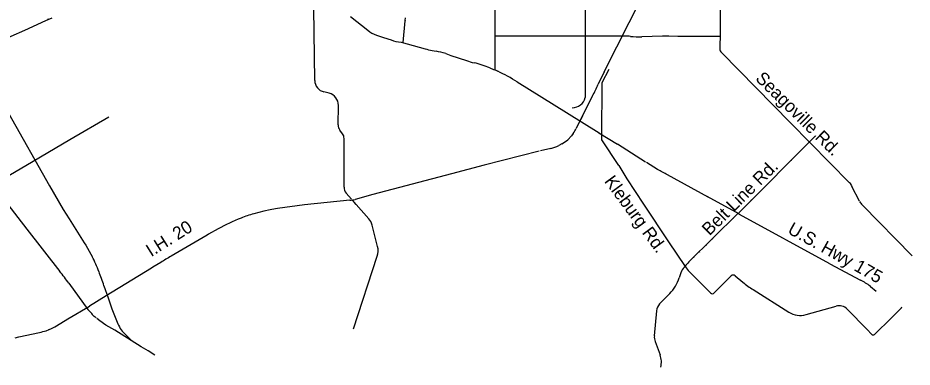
# Model space of a CAD drawing. Extents: x 105094 to 105814, y -291615 to -291123.
# Drawn here: x 105478.5 to 105563.1, y -291541 to -291508 of the extents above; entities that cross this region are included whole.
import ezdxf

# ---------------------------------------------------------------- set-up
doc = ezdxf.new("R2010")
doc.units = 0
doc.layers.add('G_MAP', color=7, linetype='Continuous')

msp = doc.modelspace()

# ---------------------------------------------------------------- linework, layer by layer
at = {"layer": 'G_MAP'}
for p, q in [((105532.097, -291466.509), (105532.215, -291515.51)), ((105534.008, -291513.065), (105538.513, -291504.143)), ((105506.612, -291513.872), (105506.522, -291507.026)), ((105479.182, -291509.112), (105481.174, -291508.211)), ((105481.174, -291508.211), (105481.762, -291507.946)), ((105481.432, -291508.143), (105481.387, -291508.059)), ((105509.99, -291507.821), (105511.634, -291509.112)), ((105514.97, -291510.304), (105515.161, -291508.247)), ((105515.165, -291508.209), (105515.214, -291507.962)), ((105476.385, -291510.349), (105479.178, -291509.112)), ((105512.464, -291509.593), (105513.113, -291509.832)), ((105513.113, -291509.832), (105513.837, -291510.042)), ((105523.79, -291509.69), (105523.674, -291509.69)), ((105535.712, -291509.689), (105523.79, -291509.69)), ((105539.514, -291509.687), (105537.56, -291509.74)), ((105514.789, -291510.259), (105517.053, -291510.888)), ((105517.725, -291511.047), (105518.093, -291511.113)), ((105506.532, -291511.428), (105506.625, -291511.428)), ((105519.007, -291511.343), (105519.508, -291511.508)), ((105519.508, -291511.508), (105520.983, -291511.999)), ((105545.101, -291511.247), (105551.638, -291517.886)), ((105523.191, -291512.703), (105523.528, -291512.839)), ((105523.528, -291512.839), (105523.761, -291512.916)), ((105523.761, -291512.916), (105523.942, -291513.007)), ((105534.008, -291513.065), (105533.443, -291514.247)), ((105525.77, -291514.016), (105529.27, -291516.191)), ((105507.979, -291515.098), (105507.484, -291514.973)), ((105532.91, -291515.352), (105531.996, -291517.131)), ((105508.83, -291518.096), (105508.847, -291516.238)), ((105529.27, -291516.191), (105531.86, -291517.796)), ((105477.644, -291516.979), (105481.513, -291523.864)), ((105531.996, -291517.131), (105531.368, -291518.414)), ((105531.96, -291517.215), (105531.783, -291517.564)), ((105531.86, -291517.796), (105533.539, -291518.849)), ((105509.243, -291518.925), (105508.993, -291518.584)), ((105557.231, -291523.567), (105551.638, -291517.886)), ((105509.383, -291523.974), (105509.39, -291519.371)), ((105530.911, -291519.111), (105530.555, -291519.489)), ((105531.068, -291518.901), (105530.911, -291519.111)), ((105533.508, -291518.833), (105535.264, -291519.896)), ((105533.787, -291519.489), (105533.787, -291519.256)), ((105535.388, -291521.94), (105533.787, -291519.489)), ((105553.994, -291519.129), (105546.735, -291526.416)), ((105554.012, -291519.13), (105553.969, -291519.171)), ((105528.943, -291520.315), (105527.972, -291520.541)), ((105530.006, -291519.877), (105529.721, -291520.027)), ((105537.925, -291521.601), (105535.264, -291519.896)), ((105479.979, -291521.549), (105476.14, -291523.793)), ((105539.062, -291522.292), (105538.015, -291521.652)), ((105551.663, -291521.426), (105551.715, -291521.5)), ((105509.348, -291522.702), (105509.409, -291522.702)), ((105519.546, -291522.705), (105512.109, -291524.688)), ((105543.858, -291524.92), (105539.998, -291522.812)), ((105509.425, -291523.629), (105509.341, -291523.632)), ((105510.077, -291525.114), (105509.59, -291524.54)), ((105558.183, -291525.319), (105557.46, -291523.922)), ((105477.347, -291525.34), (105479.363, -291527.943)), ((105509.935, -291525.224), (105505.653, -291525.66)), ((105510.342, -291525.395), (105510.2, -291525.234)), ((105510.523, -291525.608), (105510.342, -291525.395)), ((105512.109, -291524.688), (105510.439, -291525.134)), ((105546.522, -291526.374), (105543.702, -291524.827)), ((105547.881, -291525.182), (105547.936, -291525.24)), ((105482.443, -291525.563), (105482.518, -291525.505)), ((105501.801, -291526.251), (105500.84, -291526.507)), ((105502.383, -291526.128), (105501.801, -291526.251)), ((105505.653, -291525.66), (105503.078, -291526.008)), ((105511.732, -291526.962), (105510.523, -291525.608)), ((105547.407, -291525.676), (105547.445, -291525.724)), ((105563.15, -291530.472), (105558.44, -291525.674)), ((105483.37, -291526.987), (105484.785, -291529.257)), ((105546.615, -291526.516), (105542.019, -291531.059)), ((105546.147, -291526.919), (105546.192, -291526.968)), ((105546.825, -291526.551), (105546.522, -291526.374)), ((105555.361, -291531.218), (105546.829, -291526.551)), ((105479.363, -291527.943), (105482.489, -291531.947)), ((105497.464, -291527.927), (105496.556, -291528.427)), ((105512.563, -291529.597), (105512.05, -291527.561)), ((105545.672, -291527.375), (105545.727, -291527.443)), ((105496.427, -291528.515), (105493.026, -291530.51)), ((105496.556, -291528.427), (105496.43, -291528.515)), ((105544.991, -291528.037), (105545.049, -291528.101)), ((105484.785, -291529.257), (105484.937, -291529.474)), ((105484.937, -291529.474), (105485.431, -291530.32)), ((105543.628, -291529.429), (105543.677, -291529.471)), ((105544.232, -291528.835), (105544.274, -291528.88)), ((105485.431, -291530.32), (105485.557, -291530.539)), ((105510.267, -291537.384), (105512.531, -291530.503)), ((105542.989, -291530.065), (105543.034, -291530.12)), ((105492.041, -291531.101), (105491.279, -291531.557)), ((105542.459, -291530.578), (105542.52, -291530.63)), ((105555.361, -291531.218), (105558.274, -291532.784)), ((105491.153, -291531.631), (105486.868, -291534.26)), ((105491.279, -291531.557), (105491.153, -291531.631)), ((105541.256, -291532.09), (105541.109, -291532.548)), ((105541.666, -291531.46), (105541.59, -291531.56)), ((105542.063, -291531.964), (105544.083, -291533.989)), ((105544.424, -291533.989), (105546.036, -291532.374)), ((105546.393, -291532.357), (105547.124, -291532.966)), ((105483.338, -291533.068), (105485.127, -291535.542)), ((105486.668, -291533.301), (105487.055, -291534.46)), ((105548.103, -291533.677), (105551.49, -291535.806)), ((105559.198, -291533.368), (105559.754, -291533.813)), ((105486.868, -291534.26), (105485.282, -291535.228)), ((105487.055, -291534.46), (105487.407, -291535.49)), ((105540.209, -291534.049), (105539.255, -291535.032)), ((105483.244, -291536.452), (105485.282, -291535.228)), ((105485.502, -291535.945), (105485.127, -291535.542)), ((105487.407, -291535.49), (105487.912, -291536.741)), ((105553.109, -291536.039), (105555.947, -291535.237)), ((105485.922, -291536.356), (105485.754, -291536.207)), ((105538.956, -291535.688), (105538.753, -291538.047)), ((105482.182, -291537.09), (105483.244, -291536.452)), ((105478.617, -291538.148), (105480.574, -291537.718)), ((105481.184, -291537.563), (105481.464, -291537.45)), ((105490.184, -291539.072), (105487.682, -291537.518)), ((105488.629, -291537.861), (105489.322, -291538.54)), ((105478.265, -291538.235), (105478.617, -291538.148)), ((105538.825, -291538.575), (105539.3, -291539.852)), ((105490.843, -291539.475), (105490.184, -291539.072)), ((105491.487, -291539.873), (105490.843, -291539.475))]:
    msp.add_line(p, q, dxfattribs=at)
for points in [[(105523.568, -291484.076), (105523.613, -291492.654), (105523.619, -291498.845), (105523.629, -291501.2), (105523.644, -291512.878)], [(105544.911, -291500.815), (105544.985, -291509.351), (105544.957, -291510.894)], [(105536.492, -291509.712), (105536.385, -291509.703), (105535.712, -291509.689)], [(105544.978, -291509.712), (105540.98, -291509.713), (105540.118, -291509.7)], [(105533.787, -291519.256), (105533.803, -291514.079), (105534.465, -291512.803)], [(105487.136, -291517.35), (105483.422, -291519.504), (105479.979, -291521.549)], [(105527.846, -291520.574), (105522.663, -291521.885), (105519.546, -291522.705)], [(105535.388, -291521.94), (105536.154, -291523.199), (105537.73, -291525.586), (105540.1, -291529.141), (105541.682, -291531.5)], [(105481.513, -291523.864), (105482.812, -291526.086), (105483.37, -291526.987)], [(105557.002, -291535.517), (105558.906, -291537.46), (105559.315, -291537.901)], [(105559.582, -291537.907), (105561.183, -291536.33), (105562.132, -291535.409), (105562.161, -291535.303)], [(105487.682, -291537.518), (105486.848, -291537.027), (105486.264, -291536.62), (105486.002, -291536.42)]]:
    msp.add_lwpolyline(points, dxfattribs=at)
for centre, radius, start, end in [((105515.358, -291508.247), 0.197, 168.96206, 180.0046), ((105513.048, -291507.631), 2.048, 226.34667, 253.44368), ((105514.898, -291507.577), 2.683, 246.71442, 267.69103), ((105537.289, -291499.82), 9.923, 265.39461, 271.56755), ((105539.679, -291516.103), 6.419, 86.07902, 91.4732), ((105518.876, -291504.678), 6.472, 253.64051, 259.75739), ((105545.462, -291510.893), 0.506, 180.11872, 224.46064), ((105516.853, -291517.978), 6.976, 72.01939, 79.76661), ((105521.97, -291509.856), 2.359, 245.28886, 263.36797), ((105518.198, -291525.054), 13.322, 67.99004, 74.77325), ((105515.132, -291531.133), 20.153, 58.13963, 64.07876), ((105507.768, -291513.852), 1.156, 180.97602, 255.77511), ((105508.555, -291502.92), 27.343, 332.95831, 335.52819), ((105507.696, -291516.214), 1.151, 358.80352, 75.7775), ((105530.936, -291515.146), 1.33, 272.40248, 344.13858), ((105509.669, -291518.088), 0.838, 180.50155, 216.25), ((105528.587, -291517.04), 3.101, 323.11671, 333.71013), ((105508.638, -291519.371), 0.752, 0.0046, 36.36781), ((105528.847, -291517.657), 2.505, 297.57136, 313.00547), ((105528.197, -291517.113), 3.288, 283.11278, 297.60994), ((105527.601, -291544.04), 24.583, 59.71525, 62.21211), ((105556.591, -291524.232), 0.923, 19.59988, 46.08091), ((105510.257, -291523.975), 0.874, 179.9804, 220.28671), ((105509.486, -291521.274), 3.976, 276.48495, 283.86658), ((105559.499, -291524.636), 1.484, 207.43514, 224.41338), ((105504.345, -291535.413), 9.49, 97.67372, 101.93577), ((105507.052, -291545.336), 19.874, 111.90587, 118.84324), ((105503.955, -291538.188), 12.089, 104.93257, 110.92852), ((105510.67, -291527.91), 1.424, 14.16575, 41.76558), ((105510.988, -291529.995), 1.625, 341.77664, 14.16718), ((105514.31, -291567.1), 42.329, 120.18575, 121.74059), ((105465.017, -291540.578), 22.861, 22.11877, 26.04691), ((105544.69, -291533.761), 3.8, 134.67532, 142.72803), ((105465.198, -291545.935), 22.24, 35.34773, 38.97081), ((105458.474, -291542.543), 29.67, 18.15008, 20.87628), ((105542.415, -291532.46), 1.217, 131.85166, 162.26963), ((105544.269, -291529.765), 3.114, 213.8555, 224.91519), ((105537.463, -291531.382), 3.829, 315.83425, 342.26419), ((105546.224, -291532.561), 0.265, 50.25468, 135.01114), ((105552.949, -291525.968), 9.105, 230.2257, 237.84507), ((105556.026, -291537.357), 5.096, 51.51651, 63.8296), ((105544.253, -291533.819), 0.241, 224.8931, 315.05258), ((105540.023, -291535.778), 1.071, 135.82858, 175.17094), ((105556.238, -291536.266), 1.07, 44.41961, 105.77257), ((105486.433, -291535.3), 1.133, 214.70096, 233.14047), ((105552.561, -291534.102), 2.013, 237.84969, 285.78627), ((105479.55, -291532.734), 5.09, 292.08402, 301.13442), ((105490.72, -291535.732), 2.984, 199.77155, 225.51544), ((105479.632, -291532.729), 5.077, 280.69322, 287.80444), ((105539.974, -291538.149), 1.225, 175.20283, 200.33724), ((105559.451, -291537.775), 0.186, 222.81733, 314.55621), ((105537.489, -291540.527), 1.933, 345.6581, 20.44322)]:
    msp.add_arc(centre, radius, start, end, dxfattribs=at)

# ---------------------------------------------------------------- texts
for s, height, rotation, p in [('Seagoville Rd.', 1.21107, 315.35648, (105548.245, -291513.779)), ('Belt Line Rd.', 1.21107, 44.63203, (105543.971, -291528.633)), ('Kleburg Rd.', 1.21107, 306.27987, (105533.967, -291523.425)), ('I.H. 20', 1.2111, 32.26548, (105491.129, -291530.61)), ('U.S. Hwy 175', 1.21107, 330.7171, (105551.28, -291528.286))]:
    msp.add_text(s, height=height, rotation=rotation, dxfattribs=at).set_placement(p)

doc.saveas('drawing.dxf')
